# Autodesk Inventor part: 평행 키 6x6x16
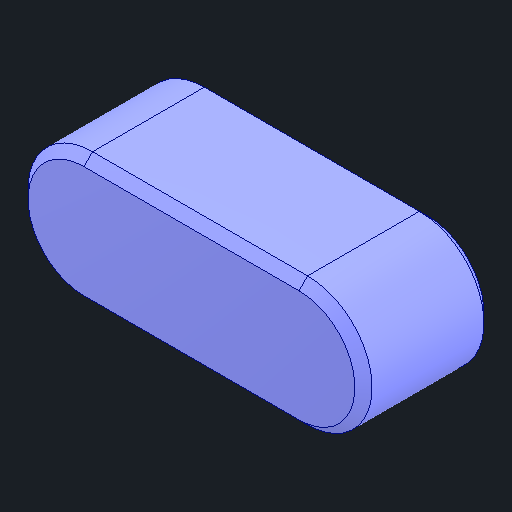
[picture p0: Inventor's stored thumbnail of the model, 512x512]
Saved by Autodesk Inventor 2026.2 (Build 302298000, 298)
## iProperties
Created: 2025-11
Part Number: 평행 키 6x6x16
Material: 강철, 연강
Description: 키 및 해당 키홈
Document SubType Name: Modeling
Designer: PC2-07
Density: 7.85 g/cm^3
Appearance: 기본값
Author: jhkim
Sending System: Autodesk Inventor 2026
Preprocessor: ST-DEVELOPER v20.1
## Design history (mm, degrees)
feature "Solid1"
node "솔리드1"
